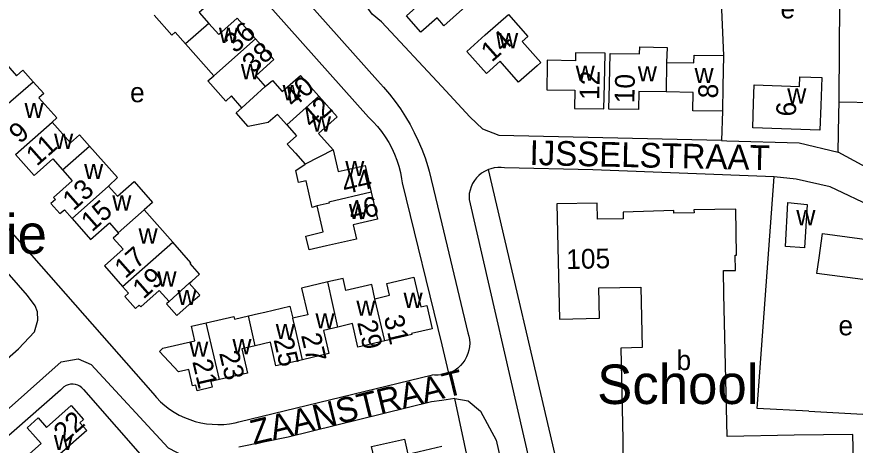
# Model space of a CAD drawing. Extents: x 156721 to 158827, y 386657 to 388950.
# Drawn here: x 157643.5 to 157813.5, y 387819.8 to 387906.7 of the extents above; entities that cross this region are included whole.
import ezdxf

# ---------------------------------------------------------------- set-up
doc = ezdxf.new("R2010")
doc.units = 0
for name, color, linetype in [('BLT_Basislijn', 7, 'Continuous'), ('BLT_Bebouwing', 7, 'Continuous'), ('BLT_Bebouwing_beschrifting', 7, 'Continuous'), ('BLT_Centroide', 7, 'Continuous'), ('BLT_Huisnummer', 7, 'Continuous'), ('BLT_Huisnummer_ tussenligend', 7, 'Continuous'), ('BLT_Onderverdeling_panden', 7, 'Continuous'), ('BLT_Straatnaam', 7, 'Continuous'), ('BLT_Terrein_beschrifting', 7, 'Continuous')]:
    doc.layers.add(name, color=color, linetype=linetype)

msp = doc.modelspace()

# ---------------------------------------------------------------- linework, layer by layer
at = {"layer": 'BLT_Basislijn'}
for p, q in [((157714.8, 387886.36), (157655.56, 387953.09)), ((157665.97, 387950.9), (157716.61, 387893.79)), ((157608.95, 387901.04), (157671.09, 387830.36)), ((157810.16, 387886.9), (157810.2, 387889.4)), ((157820.14, 387889.23), (157810.2, 387889.4)), ((157786.53, 387887.58), (157786.32, 387881.62)), ((157810.03, 387879.29), (157810.16, 387886.9)), ((157727.1, 387875.43), (157729.65, 387864.76)), ((157756.85, 387799.79), (157739.15, 387875.75)), ((157721.63, 387873.04), (157729.65, 387840.17)), ((157735.18, 387869.65), (157751.27, 387799.73)), ((157729.65, 387864.76), (157734.95, 387842.65)), ((157729.65, 387840.17), (157731.05, 387834.42)), ((157688.51, 387824.55), (157727.78, 387834.11)), ((157657.03, 387831.15), (157675.02, 387810.63)), ((157652.39, 387831.01), (157630.79, 387812.14)), ((157732.29, 387829.3), (157729.65, 387828.92)), ((157804.07, 387826.71), (157823.54, 387825.62))]:
    msp.add_line(p, q, dxfattribs=at)
for points in [[(157810.2, 387889.4), (157810.21, 387890.38), (157810.49, 387928.79)], [(157729.65, 387892.59), (157717.44, 387905.68), (157715.52, 387907.28), (157714.56, 387908.71), (157714.56, 387909.31), (157714.77, 387912.64), (157716.51, 387915.42), (157719.23, 387917.49), (157725.93, 387923.8), (157729.65, 387927.04)], [(157784.43, 387926.99), (157785.75, 387922.32), (157786.76, 387898.85)], [(157598.1, 387799.07), (157643.84, 387839.41), (157647.1, 387842.84), (157647.76, 387845.18), (157647.71, 387846.88), (157647.26, 387848.11), (157645.66, 387850.18), (157604.01, 387897.98), (157602.32, 387899.85), (157600.43, 387901.14), (157597.4, 387901.74), (157596.12, 387901.62), (157592.52, 387899.67), (157572.88, 387882.96)], [(157716.61, 387893.79), (157717.86, 387892.43), (157719.06, 387891.01), (157720.2, 387889.54), (157721.27, 387888.03), (157722.28, 387886.47), (157723.22, 387884.87), (157724.09, 387883.23), (157724.88, 387881.56), (157725.61, 387879.85), (157726.26, 387878.11), (157726.83, 387876.35), (157727.1, 387875.43)], [(157786.32, 387881.62), (157741.26, 387882.65), (157737.97, 387883.96), (157735.36, 387886.47), (157729.65, 387892.59)], [(157714.8, 387886.36), (157715.74, 387885.44), (157716.63, 387884.46), (157717.45, 387883.44), (157718.21, 387882.36), (157718.9, 387881.24), (157719.52, 387880.08), (157720.07, 387878.89), (157720.55, 387877.66), (157720.95, 387876.41), (157721.27, 387875.13), (157721.52, 387873.84), (157721.63, 387873.04)], [(157786.32, 387881.62), (157787.4, 387881.6), (157802.1, 387881.17), (157810.03, 387879.29)], [(157818.98, 387874.38), (157818.82, 387874.44), (157810.03, 387879.29)], [(157739.15, 387875.75), (157738.96, 387875.68), (157738.32, 387875.38), (157737.73, 387875), (157737.19, 387874.55), (157736.7, 387874.05), (157736.27, 387873.5), (157735.9, 387872.9), (157735.61, 387872.26), (157735.39, 387871.59), (157735.24, 387870.91), (157735.18, 387870.21), (157735.18, 387869.65)], [(157742.4, 387876.08), (157741.7, 387876.16), (157741, 387876.16), (157740.3, 387876.08), (157739.62, 387875.92), (157739.15, 387875.75)], [(157797.02, 387874.3), (157760.27, 387875.72), (157742.4, 387876.08)], [(157804.07, 387826.71), (157793.56, 387827.3), (157797.02, 387874.3)], [(157822.51, 387867.07), (157817.49, 387867.93), (157808.39, 387872.24), (157801.49, 387873.81), (157797.02, 387874.3)], [(157734.95, 387842.65), (157735.15, 387841.96), (157735.27, 387841.25), (157735.31, 387840.53), (157735.27, 387839.81), (157735.16, 387839.1), (157734.96, 387838.41), (157734.69, 387837.74), (157734.35, 387837.11), (157733.94, 387836.52), (157733.46, 387835.98), (157732.93, 387835.49), (157732.35, 387835.07), (157731.72, 387834.71), (157731.05, 387834.42)], [(157606.55, 387795.84), (157652.53, 387836.74), (157655.97, 387837.33), (157658.59, 387836.21), (157674.23, 387819.3), (157677.74, 387817.47)], [(157729.67, 387834.08), (157728.93, 387834.03), (157728.21, 387834.06), (157727.78, 387834.11)], [(157731.05, 387834.42), (157730.37, 387834.22), (157729.67, 387834.08)], [(157657.03, 387831.15), (157656.69, 387831.49), (157656.3, 387831.78), (157655.87, 387831.99), (157655.4, 387832.14), (157654.92, 387832.2), (157654.43, 387832.19), (157653.96, 387832.09), (157653.5, 387831.92), (157653.08, 387831.68), (157652.71, 387831.37), (157652.39, 387831.01)], [(157671.09, 387830.36), (157671.85, 387829.48), (157672.67, 387828.65), (157673.55, 387827.88), (157674.47, 387827.17), (157675.44, 387826.53), (157676.46, 387825.95), (157677.5, 387825.45), (157678.59, 387825.02), (157679.7, 387824.66), (157680.83, 387824.39), (157681.97, 387824.19), (157683.13, 387824.07), (157684.29, 387824.02), (157685.46, 387824.06), (157686.62, 387824.18), (157687.76, 387824.38), (157688.51, 387824.55)], [(157729.65, 387828.92), (157727.58, 387828.62), (157698.51, 387821.44), (157688.53, 387819.45)], [(157732.29, 387829.3), (157735.03, 387828.81), (157737.49, 387826.74), (157740.68, 387820.89), (157758.17, 387743.11)], [(157747.94, 387763.54), (157744.61, 387776.95), (157735.15, 387815.96), (157732.29, 387829.3)]]:
    msp.add_lwpolyline(points, dxfattribs=at)
at = {"layer": 'BLT_Bebouwing'}
for points in [[(157729.65, 387905.44), (157728.69, 387906.53), (157725.41, 387903.63), (157722.49, 387906.95), (157725.77, 387909.85), (157722.64, 387913.39), (157727.11, 387917.36), (157729.56, 387914.59), (157729.65, 387914.67)], [(157680.53, 387915.16), (157684.25, 387910.94), (157680.49, 387907.62), (157682.46, 387905.39)], [(157737.65, 387913.77), (157733.5, 387910.1), (157734.56, 387908.9), (157733.84, 387908.26), (157730.1, 387904.93), (157729.65, 387905.44)], [(157677.74, 387901.23), (157675.65, 387903.59), (157674.95, 387902.97), (157671.33, 387907.08)], [(157682.46, 387905.39), (157684.44, 387903.14), (157688.2, 387906.46), (157691.91, 387902.25)], [(157748.97, 387896.77), (157745.23, 387893.45), (157741.46, 387897.7), (157738.69, 387895.25), (157734.72, 387899.71), (157738.46, 387903.04), (157743.16, 387907.22), (157747.12, 387902.76), (157745.93, 387901.69), (157749.71, 387897.43), (157748.97, 387896.77)], [(157683.43, 387894.77), (157677.74, 387901.23)], [(157691.91, 387902.25), (157695.62, 387898.04), (157692, 387894.73), (157693.89, 387892.58)], [(157762.63, 387893.04), (157762.75, 387899.33), (157756.76, 387899.43), (157756.73, 387897.83), (157751.04, 387897.93), (157751.02, 387896.94), (157750.93, 387891.94), (157756.62, 387891.84), (157756.55, 387888.16), (157762.53, 387888.04), (157762.63, 387893.04)], [(157775.11, 387891.49), (157769.58, 387891.6), (157769.51, 387887.91), (157763.53, 387888.02), (157763.63, 387893.02), (157763.76, 387899.31), (157769.73, 387899.19), (157769.77, 387900.63), (157775.33, 387900.5), (157775.23, 387897.49)], [(157639.66, 387898.74), (157639.84, 387898.9), (157643.48, 387894.77), (157644.74, 387895.88), (157646.86, 387893.55)], [(157775.23, 387897.49), (157780.77, 387897.37), (157780.8, 387898.97), (157786.76, 387898.85)], [(157786.76, 387898.85), (157786.63, 387892.58), (157786.53, 387887.58)], [(157689.16, 387888.27), (157687.05, 387890.67), (157685.88, 387889.64), (157682.27, 387893.74), (157683.43, 387894.77)], [(157693.89, 387892.58), (157695.37, 387893.79), (157697.32, 387891.57), (157700, 387893.92), (157701.04, 387894.84), (157704.77, 387890.61)], [(157806.49, 387888.71), (157806.31, 387883.71), (157792.69, 387884.18), (157792.87, 387889.18), (157792.99, 387892.92), (157802.18, 387892.6), (157802.24, 387894.55), (157806.69, 387894.4), (157806.49, 387888.71)], [(157646.86, 387893.55), (157648.98, 387891.16), (157648.02, 387890.31), (157651.64, 387886.22), (157650.68, 387885.38)], [(157786.53, 387887.58), (157780.57, 387887.69), (157780.64, 387891.39), (157775.11, 387891.49)], [(157704.77, 387890.61), (157708.46, 387886.42), (157704.68, 387883.08), (157707.65, 387879.72)], [(157698.22, 387884.79), (157696.36, 387886.91), (157694.5, 387885.27), (157690.4, 387884.51), (157688, 387887.24), (157689.16, 387888.27)], [(157650.68, 387885.38), (157654.39, 387881.18), (157656.24, 387882.82), (157658.27, 387880.52)], [(157698.22, 387884.79), (157700.18, 387882.57), (157698.31, 387880.92), (157700, 387879.09), (157701.95, 387876.87)], [(157658.27, 387880.52), (157663.9, 387874.14), (157662.11, 387872.37)], [(157643.24, 387878.8), (157647.01, 387874.53), (157650.81, 387877.89), (157652.77, 387875.67)], [(157707.65, 387879.72), (157708.66, 387875.33), (157714.11, 387876.59), (157715.37, 387871.13)], [(157652.77, 387875.67), (157654.73, 387873.45), (157650.94, 387870.11), (157651.34, 387869.66), (157650.44, 387868.87), (157652.26, 387866.81), (157653.16, 387867.6), (157654.71, 387865.84)], [(157704.4, 387868.37), (157703.42, 387868.07), (157702.18, 387873.44), (157700.65, 387873.09), (157700.08, 387875.58), (157701.95, 387876.87)], [(157662.11, 387872.37), (157663.91, 387870.34), (157667.28, 387873.32), (157671.05, 387869.05), (157669.34, 387867.55)], [(157715.37, 387871.13), (157716.64, 387865.67), (157711.68, 387864.52), (157712.35, 387861.66), (157707.48, 387860.53), (157706.28, 387860.25), (157702.75, 387859.43), (157702.1, 387862.26), (157705.62, 387863.08), (157704.4, 387868.37)], [(157776.67, 387867.47), (157766.41, 387867.1), (157766.44, 387865.77), (157761.2, 387865.65), (157761.13, 387868.95), (157753.01, 387868.77), (157753.53, 387845.39), (157761.62, 387845.58), (157761.48, 387851.73), (157769.97, 387851.92), (157770.24, 387839.64), (157765.92, 387839.54), (157766.34, 387821.05), (157766.36, 387813.56)], [(157799.82, 387869.03), (157803.73, 387868.69), (157803.16, 387859.9), (157799.3, 387860.15), (157799.82, 387869.03)], [(157669.34, 387867.55), (157675.12, 387861.01)], [(157786.73, 387855.24), (157789.16, 387855.29), (157789.09, 387858.39), (157789.42, 387858.4), (157789.23, 387867.74), (157780.77, 387867.56), (157780.78, 387866.96), (157776.68, 387866.87), (157776.67, 387867.47)], [(157654.71, 387865.84), (157658.48, 387861.57), (157662.28, 387864.93), (157664.08, 387862.9)], [(157664.08, 387862.9), (157664.16, 387862.8), (157663.07, 387861.84), (157665.08, 387859.57), (157661.28, 387856.21), (157664.96, 387852.04)], [(157826.99, 387842.98), (157821.99, 387843.19), (157818.22, 387843.35), (157818.54, 387850.71), (157819.59, 387850.66), (157819.69, 387852.84), (157805.69, 387854.63), (157806.12, 387857.82), (157806.8, 387862.78), (157821.79, 387860.74)], [(157678.47, 387852.67), (157679, 387853.14), (157680.53, 387854.54), (157678.63, 387856.7), (157678.8, 387856.84), (157675.12, 387861.01)], [(157786.83, 387850.46), (157786.73, 387855.24)], [(157716.1, 387849.55), (157715.49, 387852.42), (157710.24, 387851.19), (157709.66, 387853.67), (157706.59, 387852.95)], [(157716.1, 387849.55), (157719.07, 387850.24), (157718.5, 387852.65), (157723.98, 387853.93), (157725.39, 387847.89), (157726.61, 387848.18), (157727.72, 387843.46), (157723.51, 387842.47), (157723.56, 387842.28), (157718.1, 387841)], [(157664.96, 387852.04), (157666.17, 387850.66), (157665.43, 387850), (157667.6, 387847.54), (157668.35, 387848.21), (157668.64, 387847.87), (157672.41, 387851.2), (157674.4, 387848.95)], [(157674.4, 387848.95), (157673.87, 387848.49), (157675.94, 387846.13), (157679.69, 387849.44), (157680.61, 387850.25), (157678.47, 387852.67)], [(157706.59, 387852.95), (157701.22, 387851.69), (157702.48, 387846.3), (157700, 387845.72), (157699.48, 387845.6)], [(157766.36, 387813.56), (157763.41, 387813.5), (157763.46, 387811.2), (157762.93, 387811.19), (157763.11, 387802.98), (157801.47, 387803.82), (157801.16, 387810.79), (157813.23, 387811.05), (157813, 387822.02), (157801.05, 387821.9), (157787.5, 387821.57), (157786.83, 387850.46)], [(157690.45, 387846.07), (157692.53, 387846.55), (157693.77, 387846.85), (157698.83, 387848.03), (157699.48, 387845.6)], [(157681.92, 387844.65), (157687.53, 387845.96), (157687.66, 387845.41), (157690.45, 387846.07)], [(157684.62, 387833.18), (157682.82, 387832.77), (157683.1, 387831.58), (157680.07, 387830.88), (157679.8, 387832.03), (157679.12, 387831.9), (157678.37, 387835.17), (157676.32, 387834.71), (157672.43, 387838.84), (157673.12, 387839.54), (157679.6, 387841.01), (157678.92, 387843.95), (157681.92, 387844.65)], [(157708.61, 387843.81), (157705.68, 387843.13), (157706.78, 387838.43), (157701.45, 387837.18)], [(157718.1, 387841), (157712.65, 387839.72), (157711.53, 387844.5), (157708.61, 387843.81)], [(157691.85, 387839.99), (157689.16, 387839.36), (157690.31, 387834.47), (157684.62, 387833.18)], [(157701.45, 387837.18), (157700, 387836.84), (157696.04, 387835.92), (157694.91, 387840.71), (157691.85, 387839.99)], [(157646.2, 387808.63), (157645.56, 387809.36), (157646.32, 387810.03), (157644.87, 387811.68), (157647, 387813.55), (157644.37, 387816.56), (157648.46, 387820.15), (157647.3, 387821.48), (157645.62, 387823.39), (157647.85, 387825.36), (157649.53, 387823.44), (157654.57, 387827.87), (157657.05, 387825.05), (157656.31, 387824.36), (157657.71, 387822.79), (157652.23, 387818.03), (157654.21, 387815.74)], [(157722.72, 387812.23), (157722.08, 387814.99), (157719.59, 387814.41), (157719.1, 387816.51), (157716.29, 387815.86), (157715.43, 387819.56), (157722.07, 387821.09), (157722.79, 387818.05), (157729.65, 387819.67)]]:
    msp.add_lwpolyline(points, dxfattribs=at)
at = {"layer": 'BLT_Onderverdeling_panden'}
for p, q in [((157682.46, 387905.39), (157677.74, 387901.23)), ((157691.91, 387902.25), (157683.43, 387894.77)), ((157775.23, 387897.49), (157775.11, 387891.49)), ((157641.33, 387888.72), (157646.86, 387893.55)), ((157693.89, 387892.58), (157689.16, 387888.27)), ((157704.77, 387890.61), (157698.22, 387884.79)), ((157643.24, 387878.8), (157650.68, 387885.38)), ((157652.77, 387875.67), (157658.27, 387880.52)), ((157707.65, 387879.72), (157701.95, 387876.87)), ((157654.71, 387865.84), (157662.11, 387872.37)), ((157664.08, 387862.9), (157669.34, 387867.55)), ((157664.96, 387852.04), (157675.12, 387861.01)), ((157674.4, 387848.95), (157678.47, 387852.67)), ((157708.61, 387843.81), (157706.59, 387852.95)), ((157718.1, 387841), (157716.1, 387849.55)), ((157691.85, 387839.99), (157690.45, 387846.07))]:
    msp.add_line(p, q, dxfattribs=at)
for points in [[(157715.37, 387871.13), (157706.79, 387869.14), (157706.84, 387868.93), (157704.4, 387868.37)], [(157701.45, 387837.18), (157700, 387843.38), (157699.48, 387845.6)], [(157684.62, 387833.18), (157681.92, 387844.65)]]:
    msp.add_lwpolyline(points, dxfattribs=at)

# ---------------------------------------------------------------- texts
at = {"layer": 'BLT_Bebouwing_beschrifting'}
msp.add_text('School', height=8, dxfattribs=at).set_placement((157761.14, 387828.19))
at = {"layer": 'BLT_Centroide'}
for s, p in [('e', (157798.29, 387906.41)), ('w', (157684.48, 387901.44)), ('w', (157741.27, 387900.34)), ('w', (157688.94, 387894.06)), ('w', (157756.8, 387893.75)), ('w', (157769.4, 387893.62)), ('w', (157780.89, 387893.28)), ('e', (157666.47, 387889.4)), ('w', (157697.4, 387889.81)), ('w', (157799.68, 387889.12)), ('w', (157645.08, 387886.2)), ('w', (157703.34, 387883.45)), ('w', (157651.08, 387879.94)), ('w', (157710.09, 387874.44)), ('w', (157657.17, 387873.8)), ('w', (157662.88, 387867.44)), ('w', (157710.82, 387865.69)), ('w', (157801.52, 387864.44)), ('w', (157668.2, 387860.72)), ('w', (157672.03, 387852)), ('w', (157676.08, 387848.27)), ('w', (157721.91, 387847.67)), ('w', (157712.34, 387846.11)), ('w', (157704.05, 387843.53)), ('e', (157810.05, 387842.12)), ('w', (157696, 387841.38)), ('w', (157687.23, 387838.3)), ('w', (157678.48, 387837.78)), ('b', (157777.23, 387835.08)), ('w', (157651.03, 387818.84))]:
    msp.add_text(s, height=4, dxfattribs=at).set_placement(p)
at = {"layer": 'BLT_Huisnummer'}
for s, rotation, p in [('14', 41.6193, (157739.79, 387897.39)), ('38', 41.3979, (157691.39, 387895.06)), ('12', 88.8771, (157761.56, 387889.82)), ('10', 88.8208, (157768.68, 387889.15)), ('8', 88.8208, (157785.63, 387890.15)), ('42', 41.3979, (157703.33, 387883.97)), ('6', 88.0057, (157801.41, 387886.46)), ('9', 41.4374, (157644.12, 387880.84)), ('13', 41.4374, (157655, 387867.25)), ('46', 13.0436, (157711.33, 387865.19)), ('105', 1.282, (157754.91, 387855.55)), ('19', 41.4374, (157669.18, 387849.33)), ('31', 283.1783, (157717.88, 387845.78)), ('25', 283.1783, (157695.54, 387841.26)), ('21', 283.1783, (157679.07, 387836.82)), ('22', 40.9684, (157653.14, 387820.15))]:
    msp.add_text(s, height=4, rotation=rotation, dxfattribs=at).set_placement(p)
at = {"layer": 'BLT_Huisnummer_ tussenligend'}
for s, rotation, p in [('36', 41.3979, (157687.77, 387899.18)), ('40', 41.3979, (157699.65, 387888.14)), ('11', 41.4374, (157647.58, 387876.3)), ('44', 13.0384, (157709.98, 387870.7)), ('15', 41.4374, (157658.75, 387862.96)), ('17', 41.4374, (157665.51, 387853.5)), ('29', 283.1783, (157712.49, 387844.75)), ('27', 283.1783, (157701.11, 387842.14)), ('23', 283.1783, (157684.51, 387838.54))]:
    msp.add_text(s, height=4, rotation=rotation, dxfattribs=at).set_placement(p)
at = {"layer": 'BLT_Straatnaam'}
for s, rotation, p in [('IJSSELSTRAAT', 358.7788, (157747.41, 387876.67)), ('ZAANSTRAAT', 13.7602, (157691.51, 387819.88))]:
    msp.add_text(s, height=5, rotation=rotation, dxfattribs=at).set_placement(p)
at = {"layer": 'BLT_Terrein_beschrifting'}
msp.add_text('Woonwagenlokatie', height=8, dxfattribs=at).set_placement((157559.24, 387858.65))

doc.saveas('drawing.dxf')
